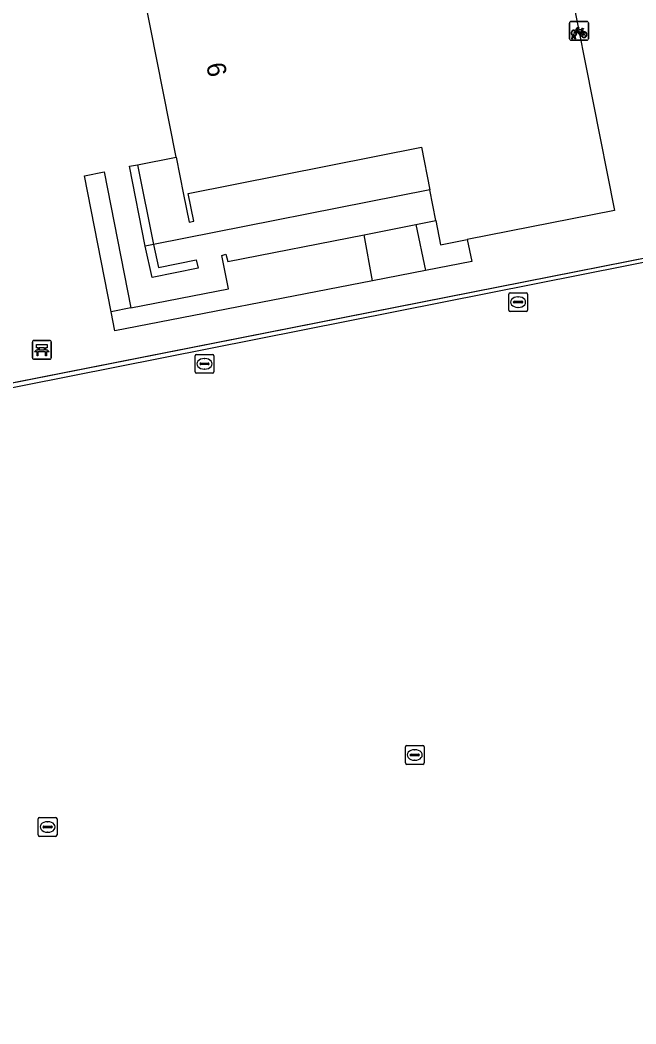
# Model space of a CAD drawing. Extents: x 160203 to 161526, y 379529 to 381797.
# Drawn here: x 160903.6 to 160936.4, y 380293.8 to 380347.2 of the extents above; entities that cross this region are included whole.
import ezdxf

# ---------------------------------------------------------------- set-up
doc = ezdxf.new("R2010")
doc.units = 0
for name, color, linetype in [('IMGEO_Bank', 7, 'Continuous'), ('IMGEO_Fietsenrek', 7, 'Continuous'), ('IMGEO_Groenvoorziening', 7, 'Continuous'), ('IMGEO_Hek', 7, 'Continuous'), ('IMGEO_Muur', 7, 'Continuous'), ('IMGEO_Pand', 7, 'Continuous'), ('IMGEO_Pand_nummerreeks', 7, 'Continuous'), ('IMGEO_Rijbaan_lokaal_open', 7, 'Continuous'), ('IMGEO_Terreindeel_open', 7, 'Continuous'), ('IMGEO_Voetpad_open', 7, 'Continuous'), ('IMGEO_Waterleidingput', 7, 'Continuous')]:
    doc.layers.add(name, color=color, linetype=linetype)

msp = doc.modelspace()

# ---------------------------------------------------------------- linework, layer by layer
at = {"layer": 'IMGEO_Bank'}
for p, q in [((160904.303, 380329.205), (160904.303, 380330.046)), ((160904.303, 380330.046), (160904.303, 380329.205)), ((160904.378, 380330.13), (160905.219, 380330.13)), ((160905.219, 380330.13), (160904.378, 380330.13)), ((160905.303, 380330.055), (160905.303, 380329.214)), ((160905.303, 380329.214), (160905.303, 380330.055)), ((160905, 380329.528), (160904.607, 380329.528)), ((160904.612, 380329.636), (160904.612, 380329.742)), ((160904.656, 380329.742), (160904.656, 380329.636)), ((160904.944, 380329.748), (160904.662, 380329.748)), ((160904.662, 380329.63), (160904.944, 380329.63)), ((160904.95, 380329.636), (160904.95, 380329.742)), ((160904.994, 380329.742), (160904.994, 380329.636)), ((160905.228, 380329.13), (160904.387, 380329.13)), ((160904.387, 380329.13), (160905.228, 380329.13))]:
    msp.add_line(p, q, dxfattribs=at)
for points in [[(160904.606, 380329.748), (160904.52, 380329.748), (160904.52, 380329.909), (160905.083, 380329.909), (160905.083, 380329.748), (160905, 380329.748)], [(160904.55, 380329.528), (160904.408, 380329.528), (160904.52, 380329.63), (160904.606, 380329.63)], [(160904.6, 380329.521), (160904.6, 380329.314), (160904.557, 380329.314), (160904.557, 380329.521)], [(160905, 380329.63), (160905.083, 380329.63), (160905.195, 380329.528), (160905.056, 380329.528)], [(160905.05, 380329.521), (160905.05, 380329.314), (160905.006, 380329.314), (160905.006, 380329.521)]]:
    msp.add_lwpolyline(points, dxfattribs=at)
for centre, radius, start, end in [((160904.381, 380330.052), 0.0779, 92.4484, 184.2845), ((160904.381, 380330.052), 0.0779, 92.4484, 184.2845), ((160905.225, 380330.052), 0.0779, 2.4484, 94.2845), ((160905.225, 380330.052), 0.0779, 2.4484, 94.2845), ((160904.55, 380329.521), 0.00671, 2.8957, 87.1043), ((160904.607, 380329.521), 0.00671, 92.8957, 177.1043), ((160904.605, 380329.741), 0.00671, 2.8957, 87.1043), ((160904.605, 380329.637), 0.00671, 272.8957, 357.1043), ((160904.662, 380329.741), 0.00671, 92.8957, 177.1043), ((160904.662, 380329.637), 0.00671, 182.8957, 267.1043), ((160904.944, 380329.741), 0.00671, 2.8957, 87.1043), ((160904.944, 380329.637), 0.00671, 272.8957, 357.1043), ((160905.001, 380329.741), 0.00671, 92.8957, 177.1043), ((160905.001, 380329.637), 0.00671, 182.8957, 267.1043), ((160904.999, 380329.521), 0.00671, 2.8957, 87.1043), ((160905.056, 380329.521), 0.00671, 92.8957, 177.1043), ((160904.381, 380329.208), 0.0779, 182.4484, 274.2845), ((160904.381, 380329.208), 0.0779, 182.4484, 274.2845), ((160905.225, 380329.208), 0.0779, 272.4484, 4.2845), ((160905.225, 380329.208), 0.0779, 272.4484, 4.2845)]:
    msp.add_arc(centre, radius, start, end, dxfattribs=at)
at = {"layer": 'IMGEO_Fietsenrek'}
for p, q in [((160932.866, 380346.175), (160932.866, 380347.016)), ((160932.866, 380347.016), (160932.866, 380346.175)), ((160932.941, 380347.1), (160933.782, 380347.1)), ((160933.782, 380347.1), (160932.941, 380347.1)), ((160933.866, 380347.025), (160933.866, 380346.184)), ((160933.866, 380346.184), (160933.866, 380347.025)), ((160932.993, 380346.184), (160933.032, 380346.344)), ((160933.062, 380346.332), (160933.027, 380346.184)), ((160933.104, 380346.356), (160933.103, 380346.36)), ((160933.145, 380346.184), (160933.111, 380346.326)), ((160933.135, 380346.367), (160933.136, 380346.36)), ((160933.143, 380346.33), (160933.178, 380346.184)), ((160933.553, 380346.649), (160933.589, 380346.554)), ((160933.791, 380346.1), (160932.95, 380346.1)), ((160932.95, 380346.1), (160933.791, 380346.1)), ((160933.027, 380346.184), (160932.993, 380346.184)), ((160933.178, 380346.184), (160933.145, 380346.184))]:
    msp.add_line(p, q, dxfattribs=at)
for points in [[(160933.2, 380346.574), (160933.148, 380346.484), (160933.108, 380346.459), (160933.109, 380346.506), (160933.164, 380346.6)], [(160933.179, 380346.626), (160933.274, 380346.79), (160933.36, 380346.776), (160933.362, 380346.767), (160933.306, 380346.756), (160933.279, 380346.711), (160933.535, 380346.67)], [(160933.475, 380346.382), (160933.425, 380346.382), (160933.234, 380346.633), (160933.215, 380346.601)], [(160933.522, 380346.645), (160933.265, 380346.686), (160933.248, 380346.657), (160933.415, 380346.437), (160933.522, 380346.645)], [(160933.57, 380346.547), (160933.54, 380346.624), (160933.431, 380346.406), (160933.474, 380346.406)], [(160933.504, 380346.406), (160933.624, 380346.405), (160933.58, 380346.519)], [(160933.6, 380346.526), (160933.655, 380346.381), (160933.505, 380346.381)], [(160933.535, 380346.67), (160933.56, 380346.719), (160933.554, 380346.723), (160933.531, 380346.727), (160933.519, 380346.734), (160933.518, 380346.737), (160933.52, 380346.742), (160933.615, 380346.727), (160933.617, 380346.717), (160933.607, 380346.704), (160933.595, 380346.698), (160933.581, 380346.704), (160933.553, 380346.649)]]:
    msp.add_lwpolyline(points, dxfattribs=at)
for centre, radius, start, end in [((160932.944, 380347.022), 0.0779, 92.4484, 184.2845), ((160932.944, 380347.022), 0.0779, 92.4484, 184.2845), ((160933.788, 380347.022), 0.0779, 2.4484, 94.2845), ((160933.788, 380347.022), 0.0779, 2.4484, 94.2845), ((160933.106, 380346.485), 0.159, 62.6766, 242.1369), ((160933.106, 380346.485), 0.129, 63.3192, 238.903), ((160933.086, 380346.356), 0.0499, 12.8025, 158.6934), ((160933.106, 380346.485), 0.159, 253.9967, 271.7867), ((160933.086, 380346.356), 0.0174, 12.8025, 163.4502), ((160933.106, 380346.485), 0.129, 253.415, 269.0204), ((160933.106, 380346.485), 0.129, 283.6043, 43.4302), ((160933.106, 380346.485), 0.159, 283.5766, 46.6042), ((160933.633, 380346.401), 0.159, 113.3408, 178.3217), ((160933.633, 380346.401), 0.159, 187.0065, 105.7708), ((160933.633, 380346.401), 0.129, 113.923, 177.9556), ((160933.633, 380346.401), 0.129, 188.6715, 104.5883), ((160932.944, 380346.178), 0.0779, 182.4484, 274.2845), ((160932.944, 380346.178), 0.0779, 182.4484, 274.2845), ((160933.788, 380346.178), 0.0779, 272.4484, 4.2845), ((160933.788, 380346.178), 0.0779, 272.4484, 4.2845)]:
    msp.add_arc(centre, radius, start, end, dxfattribs=at)
at = {"layer": 'IMGEO_Groenvoorziening'}
msp.add_lwpolyline([(160909.534, 380331.862), (160908.495, 380331.66)], dxfattribs=at)
at = {"layer": 'IMGEO_Hek'}
msp.add_lwpolyline([(160996.953, 380272.41), (160997.26, 380272.47), (160983.227, 380343.654), (160876.335, 380322.564), (160890.446, 380251.672), (160898.27, 380253.065), (160931.929, 380259.679)], dxfattribs=at)
at = {"layer": 'IMGEO_Muur'}
for points in [[(160910.303, 380335.156), (160909.463, 380339.397), (160909.891, 380339.482)], [(160909.891, 380339.482), (160910.752, 380335.245)], [(160910.752, 380335.245), (160911.004, 380334.006), (160913.015, 380334.417), (160913.112, 380333.984), (160910.669, 380333.476), (160910.303, 380335.156)], [(160910.752, 380335.245), (160910.303, 380335.156)]]:
    msp.add_lwpolyline(points, dxfattribs=at)
at = {"layer": 'IMGEO_Pand'}
for points in [[(160931.797, 380354.522), (160935.257, 380337.055), (160927.424, 380335.503)], [(160911.948, 380339.889), (160909.903, 380350.209)], [(160911.948, 380339.889), (160912.341, 380337.903), (160912.634, 380336.424), (160912.885, 380336.474), (160912.592, 380337.953), (160924.986, 380340.408), (160925.433, 380338.153)], [(160925.759, 380336.506), (160925.433, 380338.153)], [(160925.759, 380336.506), (160926.013, 380335.224), (160927.424, 380335.503)]]:
    msp.add_lwpolyline(points, dxfattribs=at)
at = {"layer": 'IMGEO_Rijbaan_lokaal_open'}
for points in [[(160983.227, 380343.654), (160898.548, 380326.947)], [(160931.881, 380259.924), (160890.678, 380251.936), (160876.624, 380322.345), (160982.946, 380343.466), (160996.889, 380272.733)]]:
    msp.add_lwpolyline(points, dxfattribs=at)
at = {"layer": 'IMGEO_Terreindeel_open'}
for points in [[(160924.694, 380336.297), (160925.206, 380333.851)], [(160922.397, 380333.305), (160921.95, 380335.76)]]:
    msp.add_lwpolyline(points, dxfattribs=at)
at = {"layer": 'IMGEO_Voetpad_open'}
for points in [[(160909.891, 380339.482), (160911.948, 380339.889)], [(160908.495, 380331.66), (160907.069, 380338.897), (160908.112, 380339.103), (160909.534, 380331.862)], [(160925.433, 380338.153), (160910.752, 380335.245)], [(160921.95, 380335.76), (160924.694, 380336.297)], [(160924.694, 380336.297), (160925.759, 380336.506)], [(160909.534, 380331.862), (160914.738, 380332.876), (160914.376, 380334.657), (160914.593, 380334.731), (160914.69, 380334.337), (160921.95, 380335.76)], [(160927.424, 380335.503), (160927.667, 380334.33), (160925.206, 380333.851)], [(160925.206, 380333.851), (160922.397, 380333.305)], [(160922.397, 380333.305), (160908.696, 380330.639), (160908.495, 380331.66)]]:
    msp.add_lwpolyline(points, dxfattribs=at)
at = {"layer": 'IMGEO_Waterleidingput'}
for p, q in [((160929.631, 380331.747), (160929.631, 380332.599)), ((160929.706, 380332.673), (160930.558, 380332.673)), ((160930.119, 380332.453), (160930.144, 380332.453)), ((160930.632, 380332.599), (160930.632, 380331.747)), ((160929.89, 380332.167), (160929.89, 380332.179)), ((160930.328, 380332.13), (160929.93, 380332.13)), ((160929.933, 380332.216), (160930.331, 380332.216)), ((160930.374, 380332.179), (160930.374, 380332.167)), ((160930.558, 380331.673), (160929.706, 380331.673)), ((160930.142, 380331.893), (160930.117, 380331.893)), ((160912.956, 380328.463), (160912.956, 380329.315)), ((160913.031, 380329.389), (160913.883, 380329.389)), ((160913.957, 380329.315), (160913.957, 380328.463)), ((160913.215, 380328.883), (160913.215, 380328.895)), ((160913.653, 380328.846), (160913.255, 380328.846)), ((160913.258, 380328.932), (160913.656, 380328.932)), ((160913.444, 380329.169), (160913.469, 380329.169)), ((160913.699, 380328.895), (160913.699, 380328.883)), ((160913.883, 380328.389), (160913.031, 380328.389)), ((160913.467, 380328.609), (160913.442, 380328.609)), ((160924.135, 380307.654), (160924.135, 380308.506)), ((160924.21, 380308.58), (160925.062, 380308.58)), ((160925.136, 380308.506), (160925.136, 380307.654)), ((160924.394, 380308.074), (160924.394, 380308.086)), ((160924.832, 380308.037), (160924.434, 380308.037)), ((160924.437, 380308.123), (160924.835, 380308.123)), ((160924.623, 380308.36), (160924.648, 380308.36)), ((160924.878, 380308.086), (160924.878, 380308.074)), ((160925.062, 380307.58), (160924.21, 380307.58)), ((160924.646, 380307.8), (160924.621, 380307.8)), ((160904.614, 380303.825), (160904.614, 380304.677)), ((160904.689, 380304.751), (160905.541, 380304.751)), ((160905.615, 380304.677), (160905.615, 380303.825)), ((160904.873, 380304.245), (160904.873, 380304.257)), ((160905.311, 380304.208), (160904.913, 380304.208)), ((160904.916, 380304.294), (160905.314, 380304.294)), ((160905.102, 380304.531), (160905.127, 380304.531)), ((160905.357, 380304.257), (160905.357, 380304.245)), ((160905.541, 380303.751), (160904.689, 380303.751)), ((160905.125, 380303.971), (160905.1, 380303.971))]:
    msp.add_line(p, q, dxfattribs=at)
for points in [[(160929.631, 380331.747), (160929.631, 380332.599)], [(160929.706, 380332.673), (160930.558, 380332.673)], [(160930.632, 380332.599), (160930.632, 380331.747)], [(160930.558, 380331.673), (160929.706, 380331.673)], [(160912.956, 380328.463), (160912.956, 380329.315)], [(160913.031, 380329.389), (160913.883, 380329.389)], [(160913.957, 380329.315), (160913.957, 380328.463)], [(160913.883, 380328.389), (160913.031, 380328.389)], [(160924.135, 380307.654), (160924.135, 380308.506)], [(160924.21, 380308.58), (160925.062, 380308.58)], [(160925.136, 380308.506), (160925.136, 380307.654)], [(160925.062, 380307.58), (160924.21, 380307.58)], [(160904.614, 380303.825), (160904.614, 380304.677)], [(160904.689, 380304.751), (160905.541, 380304.751)], [(160905.615, 380304.677), (160905.615, 380303.825)], [(160905.541, 380303.751), (160904.689, 380303.751)]]:
    msp.add_lwpolyline(points, dxfattribs=at)
for centre, radius, start, end in [((160929.708, 380332.597), 0.0765, 91.552, 178.448), ((160929.708, 380332.597), 0.0765, 91.552, 178.448), ((160930.556, 380332.597), 0.0765, 1.552, 88.448), ((160930.556, 380332.597), 0.0765, 1.552, 88.448), ((160929.93, 380332.176), 0.0403, 85.8775, 175.7526), ((160929.927, 380332.166), 0.0366, 178.938, 274.7102), ((160930.331, 380332.173), 0.043, 264.8664, 352.4533), ((160930.335, 380332.178), 0.0386, 1.7309, 96.639), ((160929.708, 380331.749), 0.0765, 181.552, 268.448), ((160929.708, 380331.749), 0.0765, 181.552, 268.448), ((160930.556, 380331.749), 0.0765, 271.552, 358.448), ((160930.556, 380331.749), 0.0765, 271.552, 358.448), ((160913.033, 380329.313), 0.0765, 91.552, 178.448), ((160913.033, 380329.313), 0.0765, 91.552, 178.448), ((160913.881, 380329.313), 0.0765, 1.552, 88.448), ((160913.881, 380329.313), 0.0765, 1.552, 88.448), ((160913.255, 380328.892), 0.0403, 85.8775, 175.7526), ((160913.252, 380328.882), 0.0366, 178.938, 274.7102), ((160913.656, 380328.889), 0.043, 264.8664, 352.4533), ((160913.66, 380328.894), 0.0386, 1.7309, 96.639), ((160913.033, 380328.465), 0.0765, 181.552, 268.448), ((160913.033, 380328.465), 0.0765, 181.552, 268.448), ((160913.881, 380328.465), 0.0765, 271.552, 358.448), ((160913.881, 380328.465), 0.0765, 271.552, 358.448), ((160924.212, 380308.504), 0.0765, 91.552, 178.448), ((160924.212, 380308.504), 0.0765, 91.552, 178.448), ((160925.06, 380308.504), 0.0765, 1.552, 88.448), ((160925.06, 380308.504), 0.0765, 1.552, 88.448), ((160924.434, 380308.083), 0.0403, 85.8775, 175.7526), ((160924.431, 380308.073), 0.0366, 178.938, 274.7102), ((160924.835, 380308.08), 0.043, 264.8664, 352.4533), ((160924.839, 380308.085), 0.0386, 1.7309, 96.639), ((160924.212, 380307.656), 0.0765, 181.552, 268.448), ((160924.212, 380307.656), 0.0765, 181.552, 268.448), ((160925.06, 380307.656), 0.0765, 271.552, 358.448), ((160925.06, 380307.656), 0.0765, 271.552, 358.448), ((160904.691, 380304.675), 0.0765, 91.552, 178.448), ((160904.691, 380304.675), 0.0765, 91.552, 178.448), ((160905.539, 380304.675), 0.0765, 1.552, 88.448), ((160905.539, 380304.675), 0.0765, 1.552, 88.448), ((160904.913, 380304.254), 0.0403, 85.8775, 175.7526), ((160904.91, 380304.244), 0.0366, 178.938, 274.7102), ((160905.314, 380304.251), 0.043, 264.8664, 352.4533), ((160905.318, 380304.256), 0.0386, 1.7309, 96.639), ((160904.691, 380303.827), 0.0765, 181.552, 268.448), ((160904.691, 380303.827), 0.0765, 181.552, 268.448), ((160905.539, 380303.827), 0.0765, 271.552, 358.448), ((160905.539, 380303.827), 0.0765, 271.552, 358.448)]:
    msp.add_arc(centre, radius, start, end, dxfattribs=at)
for centre, major_axis, ratio, start_param, end_param in [((160930.118, 380332.173), (-0.387, 0.002), 0.722429, 4.712389, 7.853982), ((160930.143, 380332.173), (-0.39, 0.002), 0.717154, 1.570796, 4.712389), ((160913.443, 380328.889), (-0.387, 0.002), 0.722429, 4.712389, 7.853982), ((160913.468, 380328.889), (-0.39, 0.002), 0.717154, 1.570796, 4.712389), ((160924.622, 380308.08), (-0.387, 0.002), 0.722429, 4.712389, 7.853982), ((160924.647, 380308.08), (-0.39, 0.002), 0.717154, 1.570796, 4.712389), ((160905.101, 380304.251), (-0.387, 0.002), 0.722429, 4.712389, 7.853982), ((160905.126, 380304.251), (-0.39, 0.002), 0.717154, 1.570796, 4.712389)]:
    msp.add_ellipse(centre, major_axis=major_axis, ratio=ratio, start_param=start_param, end_param=end_param, dxfattribs=at)

# ---------------------------------------------------------------- texts
at = {"layer": 'IMGEO_Pand_nummerreeks'}
msp.add_text('6', height=1, rotation=281.206, dxfattribs=at).set_placement((160913.54, 380344.816))

doc.saveas('drawing.dxf')
